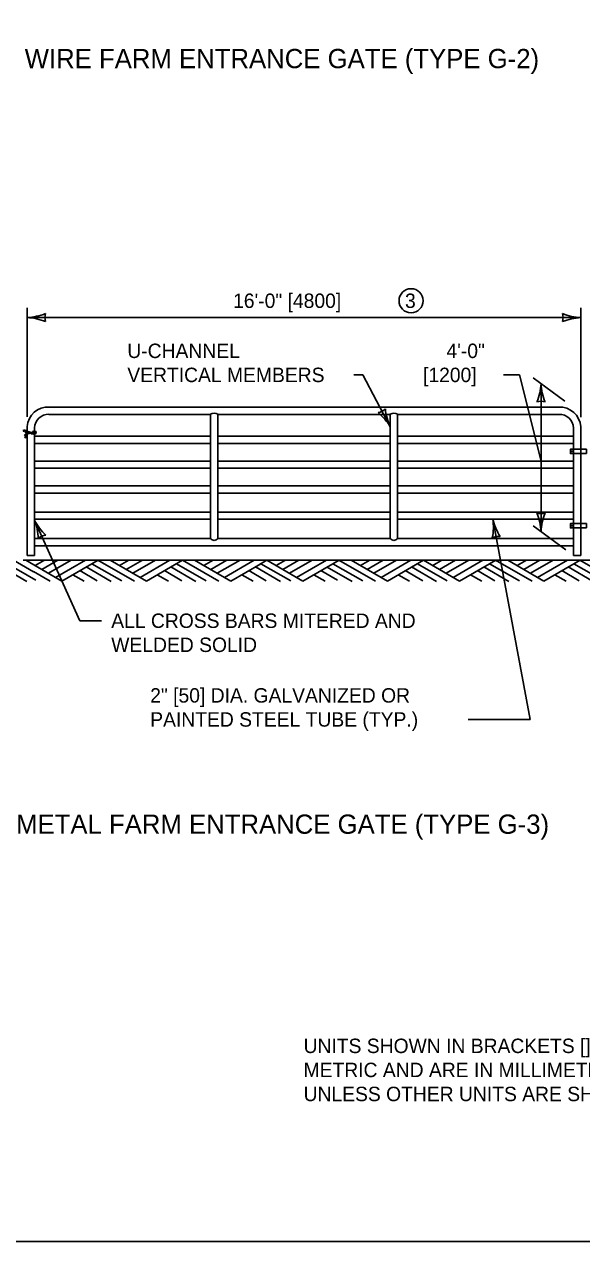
# Model space of a CAD drawing. Extents: x 49991.4 to 50021, y 49987.6 to 50011.4.
# Drawn here: x 50003.28 to 50005.6, y 50000.06 to 50005.12 of the extents above; entities that cross this region are included whole.
import ezdxf

# ---------------------------------------------------------------- set-up
doc = ezdxf.new("R2010")
doc.units = 0
for name, color, linetype in [('Level 1', 7, 'Continuous'), ('Level 2', 7, 'Continuous'), ('Level 3', 7, 'Continuous')]:
    doc.layers.add(name, color=color, linetype=linetype)

msp = doc.modelspace()

# ---------------------------------------------------------------- linework, layer by layer
at = {"layer": 'Level 1'}
for p, q in [((50003.3867, 50003.5323), (50005.5061, 50003.5323)), ((50003.3857, 50003.5023), (50004.058, 50003.5023)), ((50004.058, 50002.9859), (50004.058, 50003.5023)), ((50004.088, 50002.9859), (50004.088, 50003.5023)), ((50004.088, 50003.5023), (50004.8054, 50003.5023)), ((50004.8054, 50002.9859), (50004.8054, 50003.5023)), ((50004.8354, 50002.9859), (50004.8354, 50003.5023)), ((50004.8354, 50003.5023), (50005.5064, 50003.5023)), ((50003.2956, 50002.9158), (50003.2956, 50003.4515)), ((50003.3256, 50002.9158), (50003.3256, 50003.4461)), ((50005.5677, 50002.9158), (50005.5677, 50003.4448)), ((50005.5677, 50003.4448), (50005.5677, 50003.4448)), ((50005.5977, 50002.9158), (50005.5977, 50003.4508)), ((50003.3256, 50003.4117), (50004.058, 50003.4117)), ((50003.3256, 50003.3817), (50004.058, 50003.3817)), ((50004.088, 50003.4117), (50004.8054, 50003.4117)), ((50004.088, 50003.3817), (50004.8054, 50003.3817)), ((50004.8354, 50003.4117), (50005.5677, 50003.4117)), ((50004.8354, 50003.3817), (50005.5677, 50003.3817)), ((50003.3256, 50003.3081), (50004.058, 50003.3081)), ((50003.3256, 50003.2781), (50004.058, 50003.2781)), ((50004.088, 50003.3081), (50004.8054, 50003.3081)), ((50004.088, 50003.2781), (50004.8054, 50003.2781)), ((50004.8354, 50003.3081), (50005.5677, 50003.3081)), ((50004.8354, 50003.2781), (50005.5677, 50003.2781)), ((50003.3256, 50003.2045), (50004.058, 50003.2045)), ((50003.3256, 50003.1745), (50004.058, 50003.1745)), ((50004.088, 50003.2045), (50004.8054, 50003.2045)), ((50004.088, 50003.1745), (50004.8054, 50003.1745)), ((50004.8354, 50003.2045), (50005.5677, 50003.2045)), ((50004.8354, 50003.1745), (50005.5677, 50003.1745)), ((50003.3256, 50003.0962), (50004.058, 50003.0962)), ((50003.3256, 50003.0662), (50004.058, 50003.0662)), ((50004.088, 50003.0962), (50004.8054, 50003.0962)), ((50004.088, 50003.0662), (50004.8054, 50003.0662)), ((50004.8354, 50003.0962), (50005.5675, 50003.0962)), ((50004.8354, 50003.0662), (50005.5677, 50003.0662)), ((50003.3256, 50002.9859), (50004.058, 50002.9859)), ((50004.088, 50002.9859), (50004.8054, 50002.9859)), ((50004.8354, 50002.9859), (50005.5677, 50002.9859)), ((50003.2956, 50002.9158), (50003.3256, 50002.9158)), ((50003.3256, 50002.9559), (50005.5677, 50002.9559)), ((50005.5677, 50002.9158), (50005.5977, 50002.9158)), ((50003.1898, 50002.8676), (50003.2938, 50002.8075)), ((50003.2135, 50002.8812), (50003.3317, 50002.8129)), ((50003.2384, 50002.8961), (50003.3217, 50002.8479)), ((50003.2779, 50002.8961), (50004.5739, 50002.8961)), ((50003.2894, 50002.8961), (50003.4399, 50002.8092)), ((50003.3669, 50002.8961), (50003.3282, 50002.8737)), ((50003.423, 50002.8961), (50003.3561, 50002.8576)), ((50003.4782, 50002.8961), (50003.3838, 50002.8416)), ((50003.5373, 50002.8961), (50003.4134, 50002.8245)), ((50003.5903, 50002.8961), (50003.4399, 50002.8092)), ((50003.5409, 50002.8676), (50003.6449, 50002.8075)), ((50003.5646, 50002.8812), (50003.6889, 50002.8094)), ((50003.5895, 50002.8961), (50003.7417, 50002.8082)), ((50003.6405, 50002.8961), (50003.791, 50002.8092)), ((50003.718, 50002.8961), (50003.6793, 50002.8737)), ((50003.7741, 50002.8961), (50003.7072, 50002.8576)), ((50003.8293, 50002.8961), (50003.7349, 50002.8416)), ((50003.8884, 50002.8961), (50003.7645, 50002.8245)), ((50003.9414, 50002.8961), (50003.791, 50002.8092)), ((50003.892, 50002.8676), (50003.996, 50002.8075)), ((50003.9157, 50002.8812), (50004.04, 50002.8094)), ((50003.9406, 50002.8961), (50004.0928, 50002.8082)), ((50003.9916, 50002.8961), (50004.1421, 50002.8092)), ((50004.0691, 50002.8961), (50004.0304, 50002.8737)), ((50004.1252, 50002.8961), (50004.0583, 50002.8576)), ((50004.1804, 50002.8961), (50004.086, 50002.8416)), ((50004.2395, 50002.8961), (50004.1156, 50002.8245)), ((50004.2668, 50002.8812), (50004.1421, 50002.8092)), ((50004.2442, 50002.8682), (50004.3492, 50002.8075)), ((50004.2925, 50002.8961), (50004.2611, 50002.878)), ((50004.2668, 50002.8812), (50004.3911, 50002.8094)), ((50004.2917, 50002.8961), (50004.4422, 50002.8092)), ((50004.3692, 50002.8961), (50004.3305, 50002.8737)), ((50004.4253, 50002.8961), (50004.3584, 50002.8576)), ((50004.4805, 50002.8961), (50004.3861, 50002.8416)), ((50004.5396, 50002.8961), (50004.4157, 50002.8245)), ((50004.5927, 50002.8961), (50004.4422, 50002.8092)), ((50004.5432, 50002.8675), (50004.6472, 50002.8075)), ((50004.5669, 50002.8812), (50004.6912, 50002.8094)), ((50004.5739, 50002.8961), (50007.4579, 50002.8961)), ((50004.5918, 50002.8961), (50004.744, 50002.8082)), ((50004.6428, 50002.8961), (50004.7933, 50002.8092)), ((50004.7203, 50002.8961), (50004.6816, 50002.8737)), ((50004.7764, 50002.8961), (50004.7095, 50002.8576)), ((50004.8316, 50002.8961), (50004.7372, 50002.8416)), ((50004.8907, 50002.8961), (50004.7668, 50002.8245)), ((50004.9437, 50002.8961), (50004.7933, 50002.8092)), ((50004.8943, 50002.8676), (50004.9983, 50002.8075)), ((50004.918, 50002.8812), (50005.0423, 50002.8094)), ((50004.9429, 50002.8961), (50005.0934, 50002.8092)), ((50005.0204, 50002.8961), (50004.9817, 50002.8737)), ((50005.0765, 50002.8961), (50005.0096, 50002.8576)), ((50005.1317, 50002.8961), (50005.0373, 50002.8416)), ((50005.1908, 50002.8961), (50005.0669, 50002.8245)), ((50005.2438, 50002.8961), (50005.0934, 50002.8092)), ((50005.1944, 50002.8676), (50005.2984, 50002.8075)), ((50005.2181, 50002.8812), (50005.3424, 50002.8094)), ((50005.243, 50002.8961), (50005.3952, 50002.8082)), ((50005.294, 50002.8961), (50005.4445, 50002.8092)), ((50005.3715, 50002.8961), (50005.3328, 50002.8737)), ((50005.4276, 50002.8961), (50005.3607, 50002.8576)), ((50005.4828, 50002.8961), (50005.3884, 50002.8416)), ((50005.5419, 50002.8961), (50005.418, 50002.8245)), ((50005.5949, 50002.8961), (50005.4445, 50002.8092)), ((50005.5455, 50002.8676), (50005.6495, 50002.8075)), ((50005.5692, 50002.8812), (50005.6935, 50002.8094)), ((50005.5941, 50002.8961), (50005.7517, 50002.8051)), ((50003.3214, 50002.8482), (50003.3906, 50002.8082)), ((50003.4853, 50002.8355), (50003.5324, 50002.8082)), ((50003.5146, 50002.8524), (50003.5868, 50002.8106)), ((50003.8364, 50002.8355), (50003.8835, 50002.8082)), ((50003.8657, 50002.8524), (50003.9379, 50002.8106)), ((50004.1878, 50002.8353), (50004.2346, 50002.8082)), ((50004.2168, 50002.8523), (50004.289, 50002.8106)), ((50004.4876, 50002.8355), (50004.5347, 50002.8082)), ((50004.5169, 50002.8523), (50004.5857, 50002.8126)), ((50004.8387, 50002.8355), (50004.8858, 50002.8082)), ((50004.868, 50002.8524), (50004.9402, 50002.8106)), ((50005.1388, 50002.8355), (50005.1859, 50002.8082)), ((50005.1681, 50002.8524), (50005.2403, 50002.8106)), ((50005.4899, 50002.8355), (50005.537, 50002.8082)), ((50005.5192, 50002.8524), (50005.5914, 50002.8106))]:
    msp.add_line(p, q, dxfattribs=at)
for points in [[(50008.6146, 50011.2628), (50000.3356, 50011.2628), (50000.3356, 50000.0624), (50008.6146, 50000.0624)], [(50005.621, 50003.3389), (50005.621, 50003.3573), (50005.5547, 50003.3573), (50005.5547, 50003.3389)], [(50005.621, 50003.0299), (50005.621, 50003.0483), (50005.5547, 50003.0483), (50005.5547, 50003.0299)]]:
    msp.add_lwpolyline(points, close=True, dxfattribs=at)
for centre in [(50005.561, 50003.3485), (50005.561, 50003.0395)]:
    msp.add_circle(centre, 0.00157, dxfattribs=at)
for centre, radius, start, end in [((50003.3815, 50003.4464), 0.0861, 86.571, 176.571), ((50005.5111, 50003.4457), 0.0867, 3.3393, 93.3393), ((50003.3838, 50003.4442), 0.0582, 88.0794, 178.0794), ((50004.073, 50003.4817), 0.0255, 53.9438, 126.0562), ((50004.8204, 50003.4817), 0.0255, 53.9438, 126.0562), ((50005.5083, 50003.4429), 0.0594, 1.8321, 91.8321), ((50004.073, 50002.9969), 0.0186, 216.3275, 323.6725), ((50004.8204, 50002.9969), 0.0186, 216.3276, 323.6724)]:
    msp.add_arc(centre, radius, start, end, dxfattribs=at)
for centre in [(50003.2841, 50003.434), (50003.2897, 50003.4148), (50003.2925, 50003.4301), (50003.2928, 50003.4207), (50003.2981, 50003.428), (50003.3043, 50003.4263), (50003.3148, 50003.4239), (50003.3225, 50003.4291), (50003.3225, 50003.4232), (50003.3273, 50003.4291), (50003.328, 50003.4249), (50003.2903, 50003.4083)]:
    msp.add_ellipse(centre, major_axis=(-0.0053, 0), ratio=0.584906, dxfattribs=at)
at = {"layer": 'Level 2'}
msp.add_circle((50004.8918, 50003.9746), 0.0501, dxfattribs=at)
at = {"layer": 'Level 3'}
for p, q in [((50003.2956, 50003.4915), (50003.2956, 50003.9446)), ((50005.5977, 50003.4908), (50005.5977, 50003.9446)), ((50003.297, 50003.9046), (50005.5948, 50003.9046)), ((50004.6914, 50003.6663), (50004.6544, 50003.6663)), ((50004.8054, 50003.45), (50004.6914, 50003.6663)), ((50005.5315, 50003.5569), (50005.4002, 50003.6535)), ((50005.4324, 50003.0153), (50005.4324, 50003.6298)), ((50003.3256, 50003.0629), (50003.5135, 50002.6441)), ((50005.3878, 50002.2337), (50005.232, 50003.0662)), ((50005.5355, 50002.9395), (50005.4002, 50003.039)), ((50003.5135, 50002.6441), (50003.6047, 50002.6441)), ((50005.3878, 50002.2337), (50005.1296, 50002.2337))]:
    msp.add_line(p, q, dxfattribs=at)
msp.add_lwpolyline([(50005.4324, 50003.3081), (50005.3422, 50003.6663), (50005.2759, 50003.6663)], dxfattribs=at)
for centre, radius, start, end in [((50003.2841, 50004.1373), 0.233, 272.8273, 292.0772), ((50003.4238, 50003.9046), 0.0548, 162.1388, 197.8612), ((50005.6069, 50004.1267), 0.2223, 247.456, 267.6395), ((50005.4695, 50003.9046), 0.0548, 342.1388, 17.8612), ((50003.2864, 50003.6825), 0.2223, 67.456, 87.6395), ((50005.6092, 50003.6719), 0.233, 92.8273, 112.0772), ((50005.2103, 50003.639), 0.2223, 337.456, 357.6395), ((50005.6651, 50003.6413), 0.233, 182.8273, 202.0772), ((50004.7456, 50003.5634), 0.0548, 279.9311, 315.6534), ((50005.0062, 50003.5454), 0.2223, 185.2483, 205.4318), ((50005.4324, 50003.5016), 0.0548, 72.1388, 107.8612), ((50004.6049, 50003.3313), 0.233, 30.6196, 49.8694), ((50003.1192, 50002.9803), 0.2223, 1.6215, 21.805), ((50003.5332, 50003.1686), 0.233, 206.9928, 226.2426), ((50005.012, 50003.0343), 0.2223, 348.0563, 8.2398), ((50005.4586, 50003.1203), 0.233, 193.4276, 212.6775), ((50005.4324, 50003.1435), 0.0548, 252.1388, 287.8612), ((50005.1997, 50003.0038), 0.233, 2.8273, 22.0772), ((50005.6545, 50003.0062), 0.2223, 157.456, 177.6395), ((50003.3781, 50002.9459), 0.0548, 96.3043, 132.0266), ((50005.2556, 50002.9402), 0.0548, 82.7391, 118.4615)]:
    msp.add_arc(centre, radius, start, end, dxfattribs=at)

# ---------------------------------------------------------------- texts
at = {"layer": 'Level 2'}
for s, height, p in [('WIRE FARM ENTRANCE GATE (TYPE G-2)', 0.08, (50003.2848, 50004.9416)), ('16\'-0" [4800]', 0.06, (50004.1515, 50003.9446)), ('3', 0.06, (50004.8666, 50003.9446)), ('U-CHANNEL', 0.06, (50003.7116, 50003.7363)), ('4\'-0"', 0.06, (50005.039, 50003.7363)), ('VERTICAL MEMBERS', 0.06, (50003.7116, 50003.6363)), ('[1200]', 0.06, (50004.9416, 50003.6363)), ('ALL CROSS BARS MITERED AND', 0.06, (50003.6447, 50002.6141)), ('WELDED SOLID', 0.06, (50003.6447, 50002.5141)), ('2" [50] DIA. GALVANIZED OR', 0.06, (50003.8068, 50002.3037)), ('PAINTED STEEL TUBE (TYP.)', 0.06, (50003.8068, 50002.2037)), ('METAL FARM ENTRANCE GATE (TYPE G-3)', 0.08, (50003.249, 50001.7583)), ('UNITS SHOWN IN BRACKETS [] ARE', 0.06, (50004.4447, 50000.8465)), ('METRIC AND ARE IN MILLIMETERS (mm)', 0.06, (50004.4447, 50000.7465)), ('UNLESS OTHER UNITS ARE SHOWN.', 0.06, (50004.4447, 50000.6465))]:
    msp.add_text(s, height=height, dxfattribs=at).set_placement(p)

doc.saveas('drawing.dxf')
